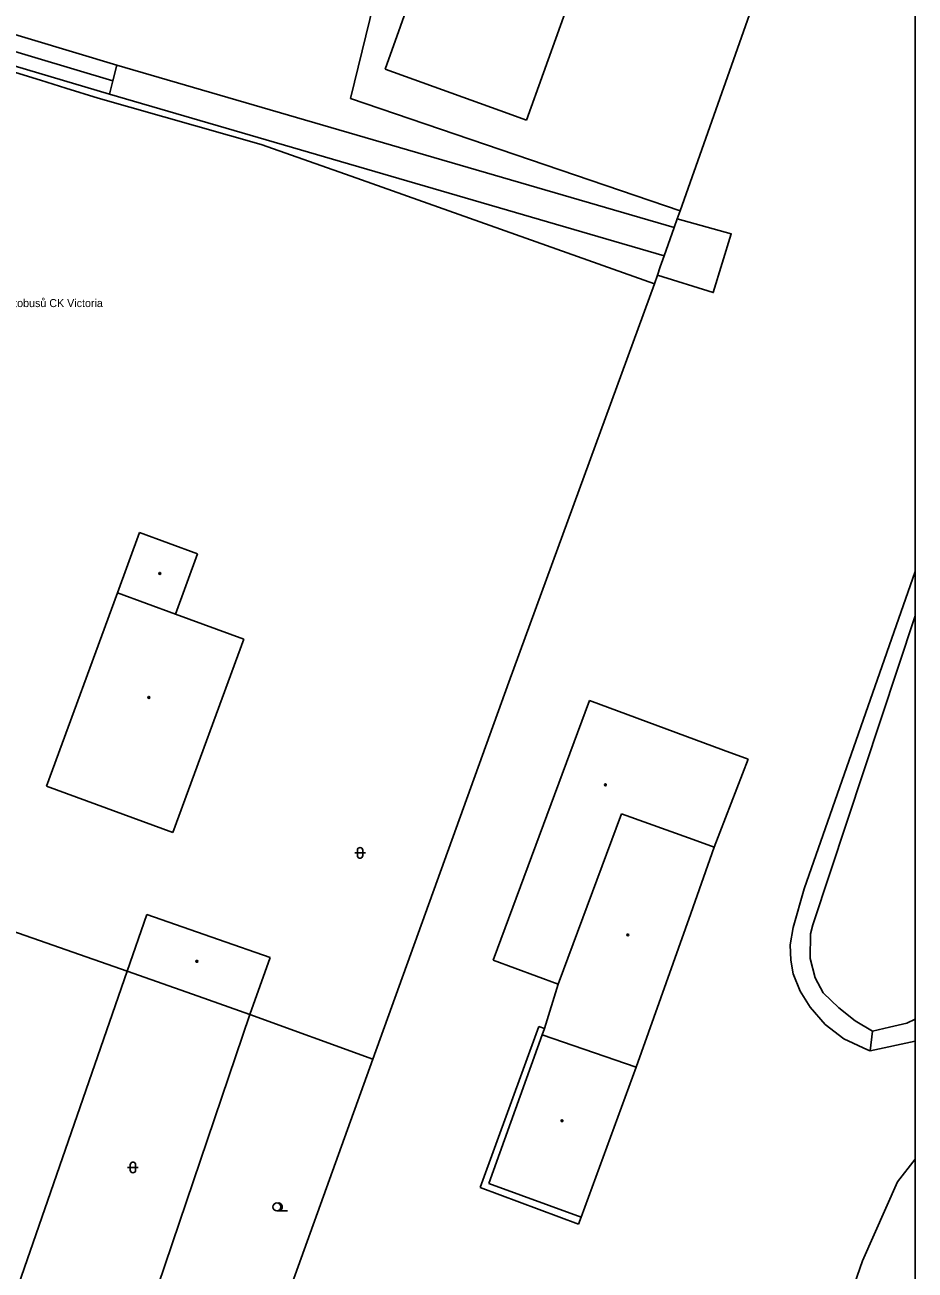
# Model space of a CAD drawing. Extents: x -599951 to -598963, y -1164095 to -1162939.
# Drawn here: x -599046.6 to -598963.2, y -1163571.5 to -1163454.9 of the extents above; entities that cross this region are included whole.
import ezdxf

# ---------------------------------------------------------------- set-up
doc = ezdxf.new("R2010")
doc.units = 0
for name, color, linetype in [('Level 11', 7, 'Continuous'), ('Level 36', 7, 'Continuous'), ('Level 39', 7, 'Continuous'), ('Level 42', 7, 'Continuous'), ('Level 51', 7, 'Continuous'), ('Level 52', 7, 'Continuous'), ('Level 54', 7, 'Continuous'), ('Vrstva 53', 7, 'Continuous')]:
    doc.layers.add(name, color=color, linetype=linetype)

msp = doc.modelspace()

# ---------------------------------------------------------------- linework, layer by layer
at = {"layer": 'Level 11'}
for points in [[(-599003.87, -1163412.18), (-599007.09, -1163424.98), (-599016.08, -1163461.76), (-598985.22, -1163472.29)], [(-599049.21, -1163453.65), (-599050.15, -1163455), (-599037.96, -1163458.64)], [(-599050.78, -1163457.77), (-599050.32, -1163456.96), (-599049.33, -1163456.84), (-599038.34, -1163460.11)], [(-599038.66, -1163461.35), (-599050.78, -1163457.77), (-599051.61, -1163459.15), (-599067.99, -1163497.5)], [(-599037.96, -1163458.64), (-599038.34, -1163460.11), (-599038.66, -1163461.35)], [(-599037.96, -1163458.64), (-598985.78, -1163473.86)], [(-599038.66, -1163461.35), (-598986.71, -1163476.5)], [(-598985.49, -1163473.05), (-598980.43, -1163474.45), (-598982.12, -1163479.95), (-598987.35, -1163478.33)]]:
    msp.add_lwpolyline(points, dxfattribs=at)
at = {"layer": 'Level 36'}
for p, q in [((-599015.69, -1163532.44), (-599014.69, -1163532.44)), ((-599015.44, -1163532.19), (-599015.44, -1163532.69)), ((-599014.94, -1163532.19), (-599014.94, -1163532.69)), ((-599036.96, -1163561.91), (-599035.96, -1163561.91)), ((-599036.71, -1163561.66), (-599036.71, -1163562.16)), ((-599036.21, -1163561.66), (-599036.21, -1163562.16)), ((-599022.98, -1163565.98), (-599021.98, -1163565.98))]:
    msp.add_line(p, q, dxfattribs=at)
msp.add_circle((-599022.98, -1163565.61), 0.375, dxfattribs=at)
for centre, radius, start, end in [((-599015.19, -1163532.19), 0.25, 0, 180), ((-599015.19, -1163532.69), 0.25, 180, 0), ((-599036.46, -1163561.66), 0.25, 0, 180), ((-599036.46, -1163562.16), 0.25, 180, 0), ((-599022.86, -1163565.61), 0.375, 260.4059, 99.5941)]:
    msp.add_arc(centre, radius, start, end, dxfattribs=at)
at = {"layer": 'Level 39'}
for centre, radius in [((-599033.95, -1163506.26), 0.09), ((-599033.95, -1163506.26), 0.0398), ((-599034.97, -1163517.88), 0.09), ((-599034.97, -1163517.88), 0.0398), ((-598992.22, -1163526.07), 0.09), ((-598992.22, -1163526.07), 0.0398), ((-598990.12, -1163540.13), 0.09), ((-598990.12, -1163540.13), 0.0398), ((-599030.47, -1163542.6), 0.09), ((-599030.47, -1163542.6), 0.0398), ((-598996.28, -1163557.53), 0.09), ((-598996.28, -1163557.53), 0.0398)]:
    msp.add_circle(centre, radius, dxfattribs=at)
at = {"layer": 'Level 51'}
for points in [[(-598985.22, -1163472.29), (-598977.06, -1163449.19), (-598963.21, -1163410.15)], [(-599050.34, -1163458.47), (-599045.11, -1163460.06)], [(-599045.11, -1163460.06), (-599042.75, -1163460.81)], [(-599039.72, -1163461.74), (-599042.75, -1163460.81)], [(-599039.72, -1163461.74), (-599024.46, -1163466.09)], [(-599024.46, -1163466.09), (-599016.03, -1163469.03)], [(-598987.63, -1163479.12), (-599016.03, -1163469.03)], [(-598987.63, -1163479.12), (-598987.35, -1163478.33), (-598987.08, -1163477.55), (-598986.71, -1163476.5), (-598985.78, -1163473.86), (-598985.49, -1163473.05), (-598985.22, -1163472.29)], [(-599001.27, -1163516.44), (-598987.63, -1163479.12)], [(-599014, -1163551.77), (-599001.27, -1163516.44)], [(-599037.01, -1163543.52), (-599049.09, -1163539.31), (-599050.22, -1163538.91)], [(-599047.75, -1163574.54), (-599037.01, -1163543.52)], [(-599025.52, -1163547.58), (-599036.11, -1163578.84)], [(-599014, -1163551.77), (-599025.52, -1163547.58)], [(-598998.44, -1163548.71), (-599003.95, -1163563.8)], [(-598997.91, -1163548.9), (-598998.44, -1163548.71)], [(-599024.78, -1163581.68), (-599014, -1163551.77)], [(-599003.95, -1163563.8), (-598994.75, -1163567.21)], [(-598994.75, -1163567.21), (-598994.5, -1163566.56)]]:
    msp.add_lwpolyline(points, dxfattribs=at)
at = {"layer": 'Level 52'}
for points in [[(-598993.24, -1163446.04), (-598999.6, -1163463.79)], [(-599012.83, -1163459.03), (-599008.52, -1163446.91)], [(-599002.09, -1163462.89), (-599012.83, -1163459.03)], [(-598999.6, -1163463.79), (-599002.09, -1163462.89)], [(-599037.91, -1163508.09), (-599035.84, -1163502.43)], [(-599035.84, -1163502.43), (-599030.41, -1163504.42)], [(-599030.41, -1163504.42), (-599032.49, -1163510.08)], [(-599044.56, -1163526.19), (-599037.91, -1163508.09)], [(-599032.49, -1163510.08), (-599037.91, -1163508.09)], [(-599032.49, -1163510.08), (-599026.08, -1163512.43)], [(-599026.08, -1163512.43), (-599032.72, -1163530.53)], [(-598993.7, -1163518.15), (-599002.73, -1163542.48)], [(-598981.15, -1163522.81), (-598993.7, -1163518.15)], [(-598978.85, -1163523.66), (-598981.15, -1163522.81)], [(-598982.04, -1163531.9), (-598978.85, -1163523.66)], [(-599032.72, -1163530.53), (-599044.56, -1163526.19)], [(-598996.64, -1163544.74), (-598990.7, -1163528.79)], [(-598990.7, -1163528.79), (-598984.01, -1163531.19)], [(-598984.01, -1163531.19), (-598982.04, -1163531.9)], [(-598982.04, -1163531.9), (-598984.22, -1163538.13)], [(-599037.01, -1163543.52), (-599035.15, -1163538.21)], [(-599035.15, -1163538.21), (-599028.46, -1163540.55)], [(-598984.22, -1163538.13), (-598989.34, -1163552.53)], [(-599028.46, -1163540.55), (-599023.6, -1163542.24)], [(-599023.6, -1163542.24), (-599025.52, -1163547.58)], [(-599002.73, -1163542.48), (-598996.64, -1163544.74)], [(-599030.34, -1163545.87), (-599037.01, -1163543.52)], [(-598997.91, -1163548.9), (-598996.64, -1163544.74)], [(-599025.52, -1163547.58), (-599030.34, -1163545.87)], [(-598998.13, -1163549.5), (-598997.91, -1163548.9)], [(-599003.12, -1163563.42), (-598998.13, -1163549.5)], [(-598989.34, -1163552.53), (-598998.13, -1163549.5)], [(-598989.34, -1163552.53), (-598994.5, -1163566.56)], [(-598994.5, -1163566.56), (-599003.12, -1163563.42)]]:
    msp.add_lwpolyline(points, dxfattribs=at)
at = {"layer": 'Level 54'}
for p, q in [((-598973.6, -1163535.81), (-598963.21, -1163506.07)), ((-598963.22, -1163510.22), (-598963.21, -1163510.21)), ((-598963.21, -1163548.02), (-598964, -1163548.4)), ((-598963.21, -1163550.09), (-598967.42, -1163550.97)), ((-598963.21, -1163561.12), (-598964.85, -1163563.27))]:
    msp.add_line(p, q, dxfattribs=at)
for points in [[(-598972.8, -1163539.19), (-598963.22, -1163510.22)], [(-598974.63, -1163539.43), (-598973.6, -1163535.81)], [(-598974.91, -1163541.05), (-598974.63, -1163539.43)], [(-598973, -1163540.02), (-598972.8, -1163539.19)], [(-598974.86, -1163542.48), (-598974.91, -1163541.05)], [(-598973.05, -1163542.34), (-598973, -1163540.02)], [(-598974.62, -1163543.77), (-598974.86, -1163542.48)], [(-598972.56, -1163544.14), (-598973.05, -1163542.34)], [(-598973.99, -1163545.41), (-598974.62, -1163543.77)], [(-598971.82, -1163545.56), (-598972.56, -1163544.14)], [(-598973.03, -1163546.88), (-598973.99, -1163545.41)], [(-598970.37, -1163546.96), (-598971.82, -1163545.56)], [(-598971.63, -1163548.52), (-598973.03, -1163546.88)], [(-598968.83, -1163548.16), (-598970.37, -1163546.96)], [(-598969.89, -1163549.87), (-598971.63, -1163548.52)], [(-598967.2, -1163549.13), (-598968.83, -1163548.16)], [(-598967.2, -1163549.13), (-598967.42, -1163550.97)], [(-598965.6, -1163548.76), (-598967.2, -1163549.13)], [(-598964, -1163548.4), (-598965.6, -1163548.76)], [(-598967.67, -1163550.89), (-598969.89, -1163549.87)], [(-598967.42, -1163550.97), (-598967.67, -1163550.89)], [(-598964.85, -1163563.27), (-598968.15, -1163570.67)], [(-598968.15, -1163570.67), (-598973.64, -1163586.47)]]:
    msp.add_lwpolyline(points, dxfattribs=at)
at = {"layer": 'Vrstva 53'}
msp.add_lwpolyline([(-599951.12, -1164094.69), (-598963.21, -1164094.69), (-598963.21, -1162939.4), (-599951.12, -1162939.4)], close=True, dxfattribs=at)

# ---------------------------------------------------------------- texts
at = {"layer": 'Level 42'}
msp.add_text('parkoviště autobusů CK Victoria', height=0.75, dxfattribs=at).set_placement((-599053.55, -1163481.31))

doc.saveas('drawing.dxf')
